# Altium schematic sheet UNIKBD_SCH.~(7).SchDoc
size A4
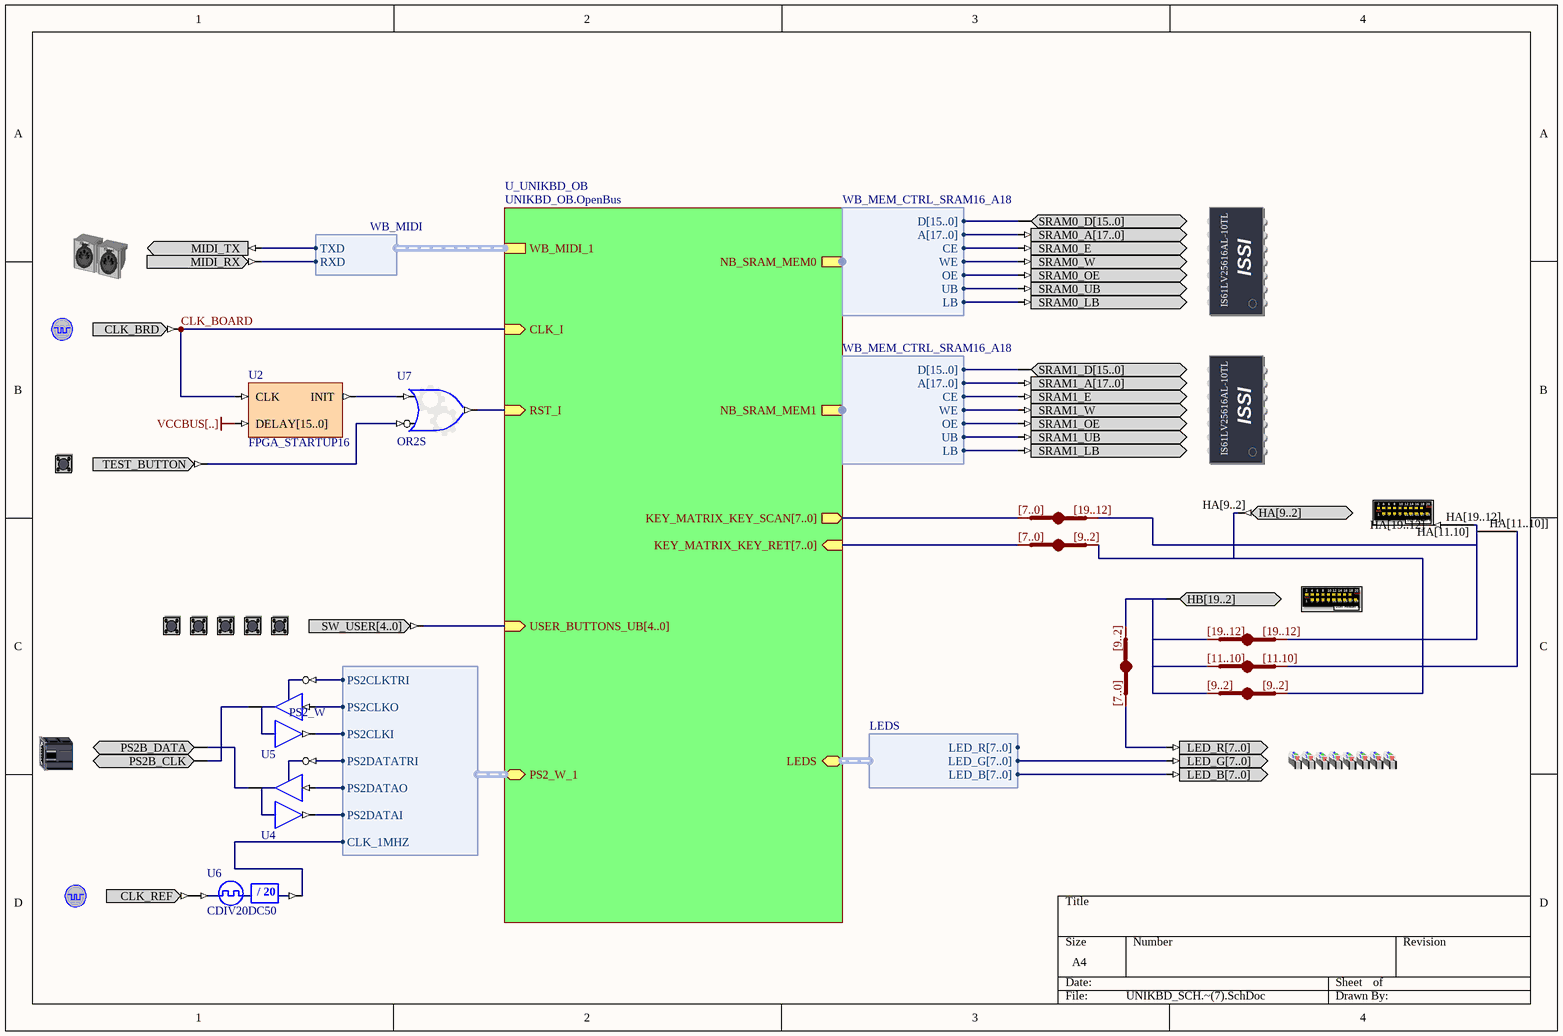
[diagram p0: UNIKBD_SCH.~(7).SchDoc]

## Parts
(Parts that share a designator on the sheet are numbered #1, #2 ... from top to bottom, then left to right.)
?#1  SRAM0  (value not drawn)
?#2  MIDI  (value not drawn)
?#3  CLOCK_BOARD  (value not drawn)
?#4  SRAM1  (value not drawn)
?#5  TEST_BUTTON  (value not drawn)
?#6  USER_HEADER_A  (value not drawn)
?#7  USER_HEADER_B  (value not drawn)
?#8  USER_BUTTONS  (value not drawn)
?#9  LEDS_RGB  (value not drawn)
?#10  PS2B  (value not drawn)
?#11  CLOCK_REFERENCE  (value not drawn)
JB_AUTO?#1  IndexA: [7..0]  IndexB: [19..12]  (hidden comment: JB)
JB_AUTO?#2  IndexA: [7..0]  IndexB: [9..2]  (hidden comment: JB)
JB_AUTO?#3  IndexA: [19..12]  (hidden comment: JB)
JB_AUTO?#4  IndexA: [7..0]  IndexB: [9..2]  (hidden comment: JB)
JB_AUTO?#5  IndexA: [11..10]  IndexB: [11.10]  (hidden comment: JB)
JB_AUTO?#6  IndexA: [9..2]  (hidden comment: JB)
U2  FPGA_STARTUP16
U4  IOBUF  (value not drawn)
U5  IOBUF  (value not drawn)
U6  CDIV20DC50
U7  OR2S

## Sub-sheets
U_UNIKBD_OB = UNIKBD_OB.OpenBus: KEY_MATRIX_KEY_SCAN[7..0] (out), KEY_MATRIX_KEY_RET[7..0] (in), WB_MIDI_1 (harness WB_MIDI), NB_SRAM_MEM0 (harness WB_MEM_CTRL_SRAM16_A18), NB_SRAM_MEM1 (harness WB_MEM_CTRL_SRAM16_A18), RST_I (in), CLK_I (in), USER_BUTTONS_UB[4..0] (in), PS2_W_1 (harness PS2_W), LEDS (harness LEDS)

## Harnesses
WB_MEM_CTRL_SRAM16_A18: D[15..0], A[17..0], CE, WE, OE, UB, LB
WB_MIDI: RXD, TXD
LEDS: LED_R[7..0], LED_G[7..0], LED_B[7..0]
PS2_W: PS2CLKTRI, PS2CLKO, PS2CLKI, PS2DATATRI, PS2DATAO, PS2DATAI, CLK_1MHZ

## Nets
VCCBUS[..]: U2.DELAY[15..0]
CLK_BOARD: ?#3.CLK_BRD U2.CLK ; sheet U_UNIKBD_OB/CLK_I
Net?#1_SRAM0_E: ?#1.SRAM0_E ; sheet U_UNIKBD_OB/NB_SRAM_MEM0.CE
Net?#1_SRAM0_LB: ?#1.SRAM0_LB ; sheet U_UNIKBD_OB/NB_SRAM_MEM0.LB
Net?#1_SRAM0_OE: ?#1.SRAM0_OE ; sheet U_UNIKBD_OB/NB_SRAM_MEM0.OE
Net?#1_SRAM0_UB: ?#1.SRAM0_UB ; sheet U_UNIKBD_OB/NB_SRAM_MEM0.UB
Net?#1_SRAM0_W: ?#1.SRAM0_W ; sheet U_UNIKBD_OB/NB_SRAM_MEM0.WE
Net?#2_MIDI_RX: ?#2.MIDI_RX ; sheet U_UNIKBD_OB/WB_MIDI_1.RXD
Net?#2_MIDI_TX: ?#2.MIDI_TX ; sheet U_UNIKBD_OB/WB_MIDI_1.TXD
Net?#4_SRAM1_E: ?#4.SRAM1_E ; sheet U_UNIKBD_OB/NB_SRAM_MEM1.CE
Net?#4_SRAM1_LB: ?#4.SRAM1_LB ; sheet U_UNIKBD_OB/NB_SRAM_MEM1.LB
Net?#4_SRAM1_OE: ?#4.SRAM1_OE ; sheet U_UNIKBD_OB/NB_SRAM_MEM1.OE
Net?#4_SRAM1_UB: ?#4.SRAM1_UB ; sheet U_UNIKBD_OB/NB_SRAM_MEM1.UB
Net?#4_SRAM1_W: ?#4.SRAM1_W ; sheet U_UNIKBD_OB/NB_SRAM_MEM1.WE
Net?#5_TEST_BUTTON: ?#5.TEST_BUTTON U7.I1
Net?#10_PS2B_CLK: ?#10.PS2B_CLK U5.IO
Net?#10_PS2B_DATA: ?#10.PS2B_DATA U4.IO
Net?#11_CLK_REF: ?#11.CLK_REF U6.CLKIN
NetU2_INIT: U2.INIT U7.I0
NetU4_I: U4.I ; sheet U_UNIKBD_OB/PS2_W_1.PS2DATAO
NetU4_O: U4.O ; sheet U_UNIKBD_OB/PS2_W_1.PS2DATAI
NetU4_T: U4.T ; sheet U_UNIKBD_OB/PS2_W_1.PS2DATATRI
NetU5_I: U5.I ; sheet U_UNIKBD_OB/PS2_W_1.PS2CLKO
NetU5_O: U5.O ; sheet U_UNIKBD_OB/PS2_W_1.PS2CLKI
NetU5_T: U5.T ; sheet U_UNIKBD_OB/PS2_W_1.PS2CLKTRI
NetU6_CLKDV: U6.CLKDV ; sheet U_UNIKBD_OB/PS2_W_1.CLK_1MHZ
NetU7_O: U7.O ; sheet U_UNIKBD_OB/RST_I

Not connected (* = marked no-connect by the designer): ?#1 SRAM0_A[17..0] SRAM0_D[15..0]; ?#4 SRAM1_A[17..0] SRAM1_D[15..0]; ?#6 HA[9..2] HA[11..10]](HA[11.10]) HA[19..12]; ?#7 HB[19..2]; ?#8 SW_USER[4..0]; ?#9 LED_B[7..0] LED_G[7..0] LED_R[7..0]; JB_AUTO?#1 A[0..0] B[0..0]; JB_AUTO?#2 A[0..0] B[0..0]; JB_AUTO?#3 A[0..0] B[0..0]; JB_AUTO?#4 A[0..0] B[0..0]; JB_AUTO?#5 A[0..0] B[0..0]; JB_AUTO?#6 A[0..0] B[0..0]

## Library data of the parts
?#1 = SRAM0: Free Static RAM - Daughterboard; PortComponent: True
?#2 = MIDI: MIDI Connector; PortComponent: True
?#3 = CLOCK_BOARD: Global System Clock Supply; PortComponent: True
?#4 = SRAM1: Free Static RAM - Daughterboard; PortComponent: True
?#5 = TEST_BUTTON: Test / Reset Button; PortComponent: True
?#6 = USER_HEADER_A: User Header A; PortComponent: True
?#7 = USER_HEADER_B: User Header B; PortComponent: True
?#8 = USER_BUTTONS: Generic User Buttons; PortComponent: True
?#9 = LEDS_RGB: LEDS RGB; PortComponent: True
?#10 = PS2B: Key Board PS2 Connector; PortComponent: True
?#11 = CLOCK_REFERENCE: Global System Clock Reference Supply; PortComponent: True
JB_AUTO?#1-JB_AUTO?#6 = JB: System BUS Joiner
U2 = FPGA_STARTUP16: FPGA Startup With 16 Bit Delay
U4 U5 = IOBUF: Input/Output Buffer; Enable: Low; Control: Common Control T; ArchiveName: GENERIC; VHDLIB_SIM: GENERIC_LIB
U6 = CDIV20DC50: Clock Divider by 20 with 50% Duty Cycle Output; DivisorRate: 20; DutyCycle: 50; ArchiveName: GENERIC; VHDLIB_SIM: GENERIC_LIB
U7 = GATE: Configurable Generic Gate; ConfiguratorName: GENERIC_GATE; ConfigurationParameters: {}Version[1.0]{}GateKind[OR]{}BusInput[False]{}GateInputType[Bit]{}GateOutputOption[Normal]{}BusWidth[8]{}RegisterOutputs[False]{}NegativeClockEdge[False]{}InputCount[2]{}InputInvert0[False]{}InputInvert1[True]{}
